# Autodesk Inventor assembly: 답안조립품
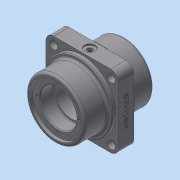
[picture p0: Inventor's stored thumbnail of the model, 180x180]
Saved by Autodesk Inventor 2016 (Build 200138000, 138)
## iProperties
Created: 2023-10
Part Number: 답안조립품
Material: 일반
Document SubType Name: Assembly
Designer: pc-2
Author: pc-2
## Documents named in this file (2)
- C:\Users\pc-2\Desktop\731006V1005\답안조립품.iam
- C:\Users\pc-2\Documents\본체.ipt
